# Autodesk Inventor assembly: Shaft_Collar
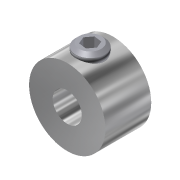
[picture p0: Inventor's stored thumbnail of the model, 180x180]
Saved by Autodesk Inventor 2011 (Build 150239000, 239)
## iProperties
Created: 2008-04
Part Number: Shaft_Collar
Document SubType Name: Assembly
Mass: 0.943808 g
Surface Area: 5.9402 cm^2
Volume: 0.571592 cm^3
Density: 1.65119 g/cm^3
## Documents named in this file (3)
- C:\Data Folder\VEX 2011\Inventor Datasets\Unit 15\Components\Shaft_Collar.iam
- C:\Data Folder\VEX 2011\Inventor Datasets\Unit 15\Components\SHAFT-COLLAR.ipt
- C:\Data Folder\VEX 2011\Inventor Datasets\Unit 15\Components\ANSI B18.3 - 8-32 UNC - 0.19(24).ipt
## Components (2 placed, 2 different names)
1. SHAFT-COLLAR:1 — Mate:1
2. Hexagon Socket Set Screw - Flat Point - Inch 8-32 UNC x 0.19:1 — Mate:1
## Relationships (1: Mate 1)
- Mate:1: SHAFT-COLLAR:1 ↔ Hexagon Socket Set Screw - Flat Point - Inch 8-32 UNC x 0.19:1
